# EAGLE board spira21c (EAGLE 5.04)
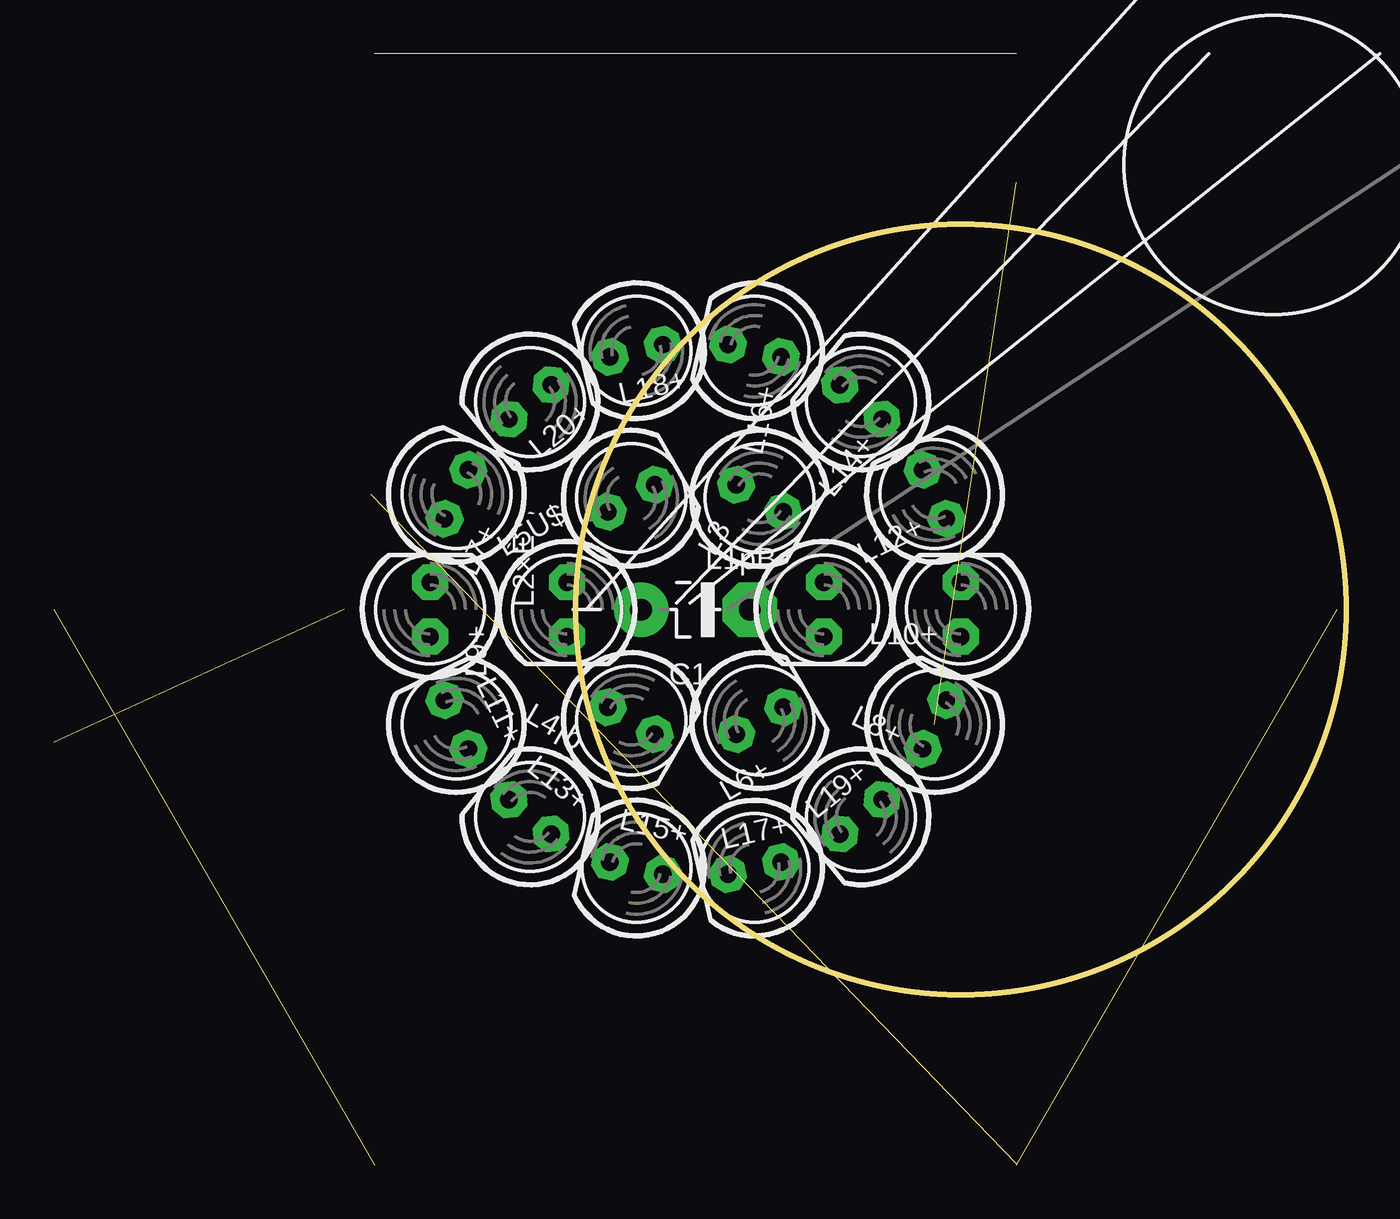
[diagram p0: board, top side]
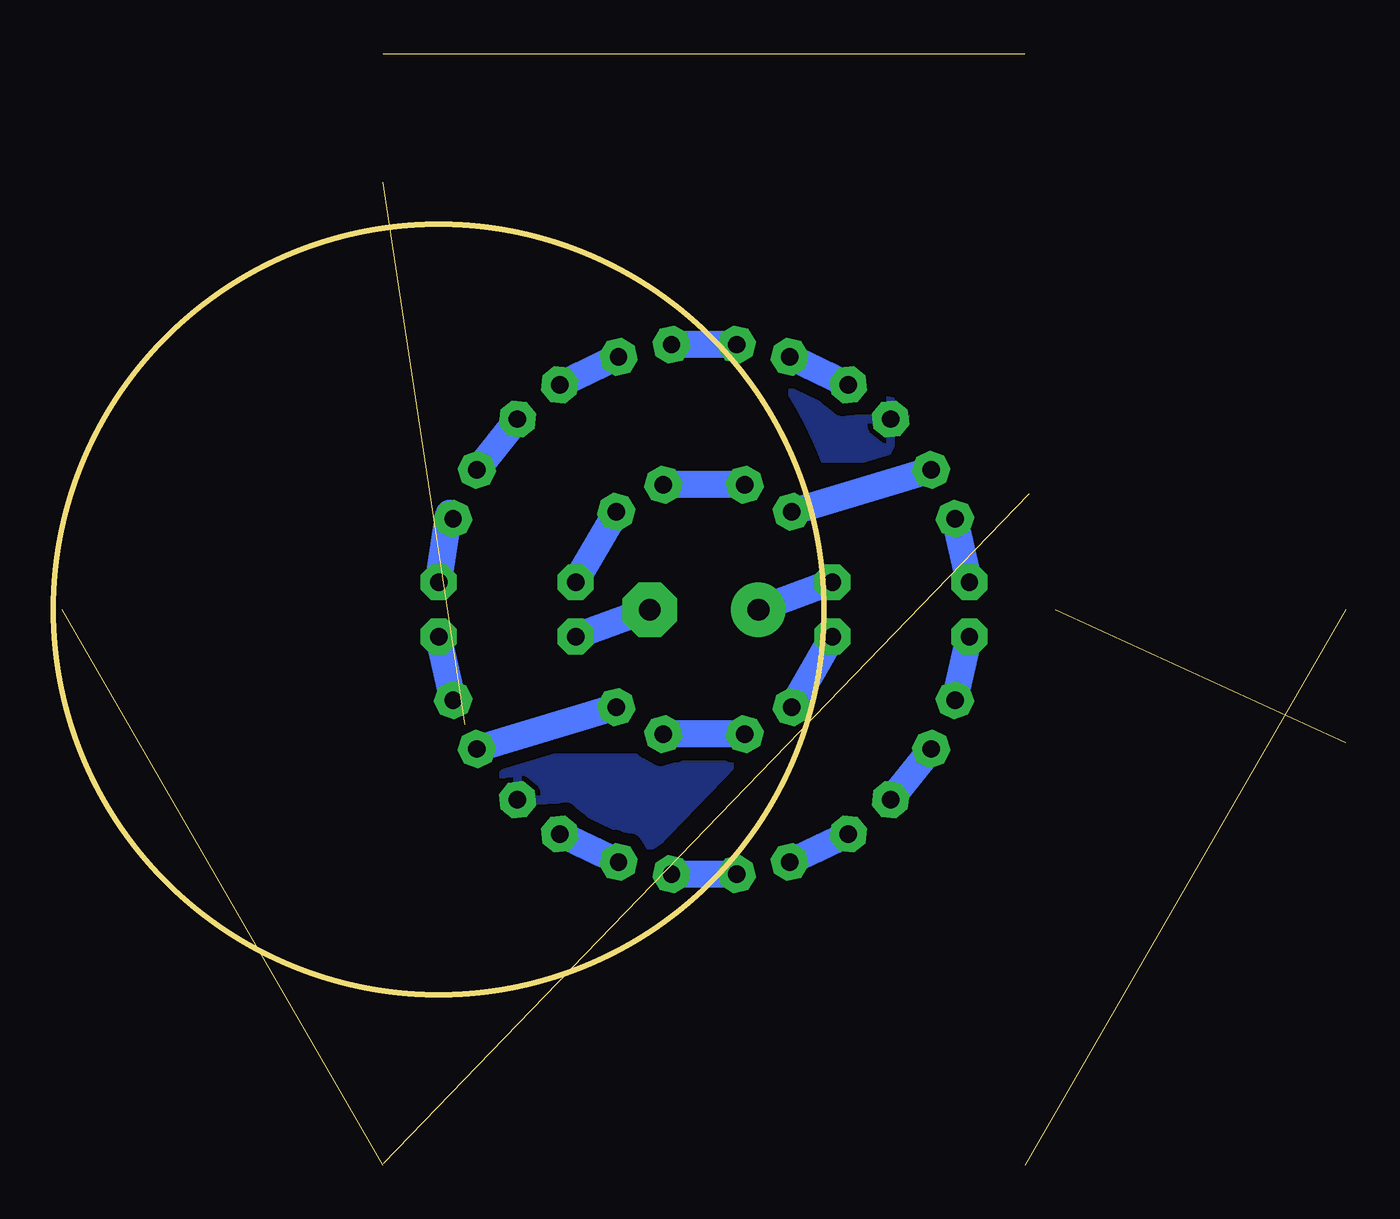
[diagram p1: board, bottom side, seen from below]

Size 60.4 x 51.96 mm. Coordinates in mm from the lower left corner, seen from the top.
Outline: 14.81,31.36 45,0.07
Outline: 45,0 60,25.98
Outline: 41.17,20.6 45,45.95
Outline: 45,51.96 15,51.96
Outline: 13.58,25.98 0,19.76
Outline: 0,25.98 15,0
Outline: circle at 42.4,25.98 radius 18
Copper layers (1*16): Top 0.035mm / dielectric 1.5mm / Bottom 0.035mm
Design rules "default": minimum track width 10mil, minimum drill 24mil, track to track 8mil, track to pad 8mil, pad to pad 8mil, via to via 8mil, smd to smd 8mil, copper to edge 40mil, drill to drill 8mil, minimum pad ring 10mil, minimum via ring 8mil, stop-mask expansion 4mil, vias tented up to drill 0mil, thermal gap 10mil

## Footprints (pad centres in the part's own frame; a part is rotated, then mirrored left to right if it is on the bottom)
E5-13 = drill 1.016 pad 2.54 round: + -2.54,0 | drill 1.016 pad 2.54 octagon: - 2.54,0
LED5MM = drill 0.813 pad 1.676 octagon: A -1.27,0; K 1.27,0

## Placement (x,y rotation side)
C1  [E5-13]  30,25.97 0 top
L1pB    [LED5MM]  36,25.98 270 top
L2×È    [LED5MM]  24,25.98 270 top
L3    [LED5MM]  33,31.18 330 top
L4¡b    [LED5MM]  27,20.78 330 top
L5Ù$    [LED5MM]  27,31.18 30 top
L6+  [LED5MM]  33,20.78 30 top
L7+  [LED5MM]  18.83,31.36 64 top
L8+  [LED5MM]  41.17,20.6 64 top
L9+  [LED5MM]  17.6,25.98 90 top
L10+  [LED5MM]  42.4,25.98 90 top
L11+  [LED5MM]  18.83,20.6 116 top
L12+  [LED5MM]  41.17,31.36 116 top
L13+  [LED5MM]  22.27,16.29 141 top
L14+  [LED5MM]  37.73,35.67 141 top
L15+  [LED5MM]  27.24,13.89 167 top
L16+  [LED5MM]  32.76,38.07 167 top
L17+  [LED5MM]  32.76,13.89 193 top
L18+  [LED5MM]  27.24,38.07 193 top
L19+  [LED5MM]  37.73,16.29 219 top
L20+  [LED5MM]  22.27,35.67 219 top

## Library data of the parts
C1 = rcl-2
L1pB L2×È L3 L4¡b L5Ù$ L6+ L7+ L8+ L9+ L10+ L11+ L12+ L13+ L14+ L15+ L16+ L17+ L18+ L19+ L20+ = led(2)

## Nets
N$1: C1.+ L2×È.A
N$2: L2×È.K L4¡b.A
N$3: L4¡b.K L6+.A
N$4: L6+.K L8+.A
N$5: L8+.K L10+.A
N$6: L1pB.A L3.K
N$7: C1.- L1pB.K
N$8: L3.A L5Ù$.K
N$9: L7+.A L9+.K
N$10: L5Ù$.A L7+.K
N$11: L9+.A L11+.K
N$12: L11+.A L13+.K
N$13: L10+.K L12+.A
N$14: L12+.K L14+.A
N$15: L14+.K L16+.A
N$16: L16+.K L18+.A
N$17: L18+.K L20+.A
N$18: L13+.A L15+.K
N$19: L15+.A L17+.K
N$20: L17+.A L19+.K
N$21: L19+.A L20+.K

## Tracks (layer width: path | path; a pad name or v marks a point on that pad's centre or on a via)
N$1
  Bottom 1.27: L2×È.A C1.+
N$2
  Bottom 1.27: L4¡b.A L2×È.K
N$3
  Bottom 1.27: L4¡b.K L6+.A
N$4
  Bottom 1.27: L6+.K L8+.A
N$5
  Bottom 1.27: L8+.K L10+.A
N$6
  Bottom 1.27: L1pB.A L3.K
N$7
  Bottom 1.27: C1.- L1pB.K
N$8
  Bottom 1.27: L5Ù$.K L3.A
N$9
  Bottom 1.27: L9+.K L7+.A
N$10
  Bottom 1.27: L7+.K L5Ù$.A
N$11
  Bottom 1.27: L11+.K L9+.A
N$12
  Bottom 1.27: L13+.K L11+.A
N$13
  Bottom 0.406: 41.91,30.48 L12+.A
  Bottom 1.27: L10+.K 41.91,30.48
N$14
  Bottom 1.27: L12+.K L14+.A
N$15
  Bottom 1.27: L16+.A L14+.K
N$16
  Bottom 1.27: L18+.A L16+.K
N$17
  Bottom 1.27: L20+.A L18+.K
N$18
  Bottom 1.27: L15+.K L13+.A
N$19
  Bottom 1.27: L15+.A L17+.K
N$20
  Bottom 1.27: L17+.A L19+.K
N$21
  pour Bottom (isolate 0.61): 20.32,35.56 27.94,36.83 34.29,36.83 40.64,30.48 41.91,22.86 39.37,20.32 33.02,22.86 22.86,27.94 26.67,19.05 35.56,19.05 39.37,19.05 39.37,17.78 31.75,13.97 21.59,17.78 17.78,25.4 19.05,33.02 27.94,29.21 33.02,25.4 36.83,24.13 36.83,27.94 31.75,33.02 24.13,33.02 21.59,33.02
